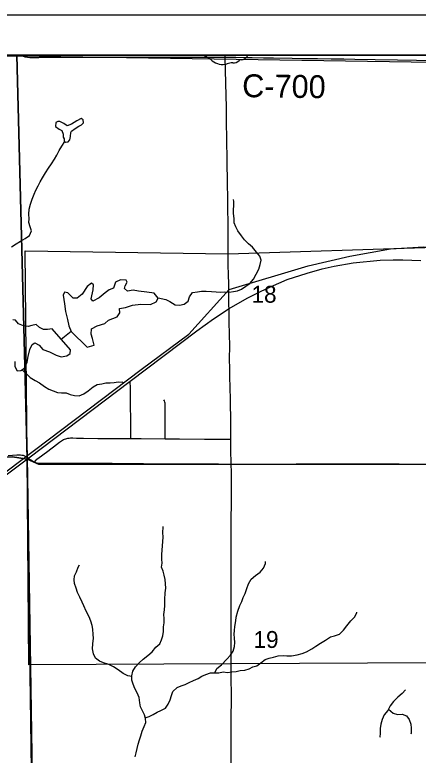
# Model space of a CAD drawing. Extents: x 0 to 34, y 0 to 22.
# Drawn here: x 3.028 to 4.028, y 19.165 to 21 of the extents above; entities that cross this region are included whole.
import ezdxf

# ---------------------------------------------------------------- set-up
doc = ezdxf.new("R2010")
doc.units = 0
for name, color, linetype in [('Default', 7, 'Continuous'), ('GM_X_City_Street', 7, 'Continuous'), ('GM_X_Corporation', 7, 'Continuous'), ('GM_X_Corporation_Text', 7, 'Continuous'), ('GM_X_County_Road', 7, 'Continuous'), ('GM_X_County_Road_Text', 7, 'Continuous'), ('GM_X_Interstate_Route', 7, 'Continuous'), ('GM_X_Minor_Lake', 7, 'Continuous'), ('GM_X_Minor_River', 7, 'Continuous'), ('GM_X_Rail_Line', 7, 'Continuous'), ('GM_X_Section', 7, 'Continuous'), ('GM_X_Section_Text', 7, 'Continuous'), ('GM_X_State_Route', 7, 'Continuous'), ('GM_X_Township_Road', 7, 'Continuous'), ('SH_Cut_Line', 7, 'Continuous'), ('SH_Data', 7, 'Continuous')]:
    doc.layers.add(name, color=color, linetype=linetype)

msp = doc.modelspace()

# ---------------------------------------------------------------- linework, layer by layer
at = {"layer": 'Default'}
for points in [[(3.0341, 20.9), (2.1, 20.9), (2.1, 20.8702), (2.5271, 20.8724), (2.8601, 20.8963), (3.0341, 20.898)], [(2.1, 20.8702), (2.1, 19.8813), (2.4888, 19.8857), (3.0228, 19.9046), (3.0592, 19.8987), (3.0341, 20.898), (2.8601, 20.8963), (2.5271, 20.8724)], [(4.0643, 20.9), (3.0341, 20.9), (3.0341, 20.898), (4.0647, 20.8827)], [(2.1, 19.8813), (2.1, 18.8733), (3.073, 18.8909), (3.0592, 19.8987), (3.0228, 19.9046), (2.4888, 19.8857)]]:
    msp.add_lwpolyline(points, close=True, dxfattribs=at)
at = {"layer": 'GM_X_City_Street'}
for points in [[(3.3157, 19.9496), (3.3159, 19.9674), (3.3146, 20.0609), (3.3145, 20.0765), (3.3144, 20.089), (3.3143, 20.0921)], [(3.4004, 19.949), (3.4005, 19.9557), (3.4008, 19.987), (3.4011, 20.0276), (3.401, 20.0339), (3.4008, 20.037), (3.4002, 20.04), (3.3989, 20.0429), (3.3972, 20.0457)], [(3.0772, 19.8914), (3.0802, 19.8952), (3.0831, 19.8983), (3.0853, 19.9003), (3.1099, 19.9184), (3.1172, 19.9239), (3.1244, 19.9293), (3.1391, 19.9403), (3.1466, 19.9456), (3.1491, 19.9471), (3.1517, 19.9483), (3.1542, 19.9493), (3.1569, 19.95), (3.1598, 19.9505), (3.1628, 19.9509), (3.1658, 19.951), (3.172, 19.9511), (3.1809, 19.9509), (3.198, 19.9507), (3.2336, 19.9501), (3.252, 19.95), (3.2862, 19.9498), (3.3157, 19.9496), (3.3409, 19.9495), (3.4004, 19.949), (3.4021, 19.949), (3.4363, 19.9491), (3.4985, 19.9484), (3.539, 19.9482), (3.5545, 19.9479), (3.5636, 19.9478)]]:
    msp.add_lwpolyline(points, dxfattribs=at)
at = {"layer": 'GM_X_Corporation'}
msp.add_lwpolyline([(4.0712, 19.394), (3.5643, 19.3915), (3.0631, 19.3888), (3.0588, 19.9042), (3.0542, 20.415), (3.5567, 20.4072), (4.0701, 20.4238), (4.0786, 19.8867)], close=True, dxfattribs=at)
at = {"layer": 'GM_X_Corporation_Text'}
msp.add_line((3.6067, 20.9), (3.493, 20.9), dxfattribs=at)
for centre, radius, start, end in [((3.4744, 20.8396), 0.0632, 47.1842, 72.9177), ((3.5428, 20.9169), 0.0401, 230.7004, 286.2918), ((3.5689, 20.9019), 0.0214, 268.777, 315.5493), ((3.5882, 20.8826), 0.00601, 65.7517, 132.6484), ((3.5856, 20.9101), 0.0226, 282.8732, 323.2771), ((3.6342, 20.8733), 0.0383, 135.8731, 142.5768), ((3.5659, 20.8477), 0.0329, 85.6951, 111.21)]:
    msp.add_arc(centre, radius, start, end, dxfattribs=at)
at = {"layer": 'GM_X_County_Road'}
for points in [[(3.5498, 20.8951), (3.5761, 20.8947), (3.5948, 20.8943), (3.6165, 20.894), (3.6444, 20.8934), (3.6693, 20.8931), (3.7159, 20.8923), (3.7407, 20.8918), (3.778, 20.8913), (3.8121, 20.8908), (3.8432, 20.8905), (3.8712, 20.89), (3.9209, 20.8893), (3.9768, 20.888), (4.0234, 20.8873), (4.0575, 20.8869)], [(3.0114, 19.908), (3.0331, 19.909), (3.0423, 19.9089), (3.0455, 19.9087), (3.0485, 19.9084), (3.0524, 19.9071), (3.056, 19.9055), (3.059, 19.9036)], [(3.059, 19.9036), (3.0641, 19.8994), (3.0666, 19.8975), (3.0692, 19.8957), (3.0747, 19.8925), (3.0772, 19.8914)], [(3.0772, 19.8914), (3.0805, 19.8901), (3.0836, 19.8893), (3.0868, 19.8888), (3.0899, 19.8886), (3.1117, 19.8884), (3.1488, 19.8885), (3.1705, 19.8884), (3.1984, 19.8883), (3.2294, 19.8882), (3.2697, 19.8883), (3.31, 19.8878), (3.3472, 19.8874), (3.4092, 19.887), (3.4433, 19.887), (3.4805, 19.8867), (3.5332, 19.8867), (3.5641, 19.886)], [(3.5641, 19.886), (3.5756, 19.8859), (3.5943, 19.886), (3.6161, 19.8861), (3.6566, 19.8863), (3.7251, 19.8868), (3.7624, 19.8868), (3.7935, 19.8869), (3.834, 19.8871), (3.8776, 19.8872), (3.9118, 19.8871), (3.9803, 19.8869), (4.0788, 19.8862)]]:
    msp.add_lwpolyline(points, dxfattribs=at)
at = {"layer": 'GM_X_Interstate_Route'}
msp.add_lwpolyline([(3.0331, 20.9), (2.1, 20.9), (2.1, 16.8784), (2.6014, 16.878), (3.0939, 16.8719), (3.0724, 18.2926), (3.0747, 18.8969), (3.067, 19.3838), (3.0588, 19.9042)], close=True, dxfattribs=at)
msp.add_lwpolyline([(8.1285, 16.8707), (8.1148, 17.8694), (8.0976, 18.2853), (8.0958, 18.3144), (8.0817, 18.88), (8.0959, 19.2713), (8.1023, 19.3817), (8.0929, 19.6339), (8.0678, 20.8562), (8.0675, 20.8733), (8.067, 20.8954), (8.0669, 20.9), (3.0331, 20.9), (3.0588, 19.9042), (3.067, 19.3838), (3.0747, 18.8969), (3.0724, 18.2926), (3.0939, 16.8719)], dxfattribs=at)
at = {"layer": 'GM_X_Minor_Lake'}
for points in [[(3.1534, 20.6844), (3.1606, 20.6854), (3.1645, 20.6903), (3.1664, 20.6986), (3.1669, 20.7085), (3.1684, 20.7115), (3.1776, 20.7183), (3.1871, 20.7239), (3.1932, 20.7276), (3.1982, 20.7321), (3.1975, 20.7393), (3.1926, 20.7428), (3.1819, 20.7372), (3.1686, 20.7286), (3.158, 20.7249), (3.1497, 20.7303), (3.1395, 20.7353), (3.1346, 20.7358), (3.1296, 20.7328), (3.1292, 20.7233), (3.1382, 20.7164), (3.1446, 20.7129), (3.1479, 20.7038), (3.1482, 20.6969), (3.1501, 20.6924), (3.1504, 20.687)], [(3.1504, 20.687), (3.1534, 20.6844)]]:
    msp.add_lwpolyline(points, dxfattribs=at)
at = {"layer": 'GM_X_Minor_River'}
for points in [[(3.0198, 20.4246), (3.0316, 20.4325), (3.0423, 20.4392), (3.0541, 20.4455), (3.0644, 20.453), (3.0694, 20.4647), (3.0665, 20.4742), (3.0631, 20.4849), (3.0636, 20.4944), (3.0633, 20.5061), (3.0638, 20.5179), (3.0669, 20.5304), (3.0712, 20.5432), (3.0762, 20.5553), (3.0805, 20.5655), (3.0863, 20.5761), (3.0913, 20.5859), (3.097, 20.5957), (3.1043, 20.6086), (3.112, 20.6195), (3.1193, 20.6308), (3.1266, 20.6425), (3.1323, 20.6523), (3.1385, 20.664), (3.1447, 20.6746), (3.1521, 20.6856)], [(3.3833, 20.2983), (3.4027, 20.2942), (3.4125, 20.2895), (3.4253, 20.2814), (3.4367, 20.2802), (3.448, 20.2827), (3.4579, 20.2902), (3.4607, 20.3008), (3.4687, 20.3114), (3.4812, 20.3135), (3.4907, 20.3146), (3.5021, 20.3148), (3.5153, 20.3143), (3.5388, 20.3126), (3.5486, 20.3129), (3.5596, 20.3128), (3.5699, 20.3138), (3.5797, 20.316), (3.59, 20.32), (3.601, 20.3272), (3.6105, 20.3343), (3.6193, 20.3448), (3.6266, 20.3573), (3.6328, 20.3697), (3.6359, 20.3807), (3.6383, 20.392), (3.6354, 20.4019), (3.6271, 20.4115), (3.617, 20.4237), (3.6072, 20.4326), (3.5975, 20.4425), (3.59, 20.4521), (3.581, 20.4647), (3.5761, 20.4742), (3.5721, 20.4845), (3.5714, 20.4951), (3.5704, 20.5073), (3.5704, 20.5172), (3.5709, 20.5266), (3.571, 20.5369), (3.5703, 20.5422)], [(3.2074, 20.1762), (3.2245, 20.1813), (3.2205, 20.1977), (3.2176, 20.2087), (3.218, 20.2216), (3.2325, 20.2294), (3.2511, 20.2346), (3.2606, 20.2432), (3.2819, 20.2513), (3.2881, 20.2615), (3.2878, 20.2718), (3.3022, 20.2743), (3.32, 20.2805), (3.3405, 20.2826), (3.3643, 20.282), (3.3788, 20.2887), (3.3838, 20.2978), (3.3737, 20.3096), (3.3551, 20.3125), (3.3343, 20.3146), (3.3215, 20.317), (3.3071, 20.3148), (3.2999, 20.3217), (3.3015, 20.3282), (3.3069, 20.3372), (3.3039, 20.3418), (3.2899, 20.3434), (3.2781, 20.3375), (3.273, 20.322), (3.2617, 20.3183), (3.2518, 20.3112), (3.2369, 20.2984), (3.2213, 20.2902), (3.2172, 20.296), (3.2227, 20.3183), (3.2228, 20.3308), (3.2183, 20.335), (3.2072, 20.3264), (3.1949, 20.3072), (3.1827, 20.2974), (3.1725, 20.2979), (3.1597, 20.3106), (3.151, 20.3125), (3.1479, 20.305), (3.1515, 20.2833), (3.154, 20.2643), (3.1588, 20.2449), (3.1621, 20.229), (3.1676, 20.2153)], [(3.028, 20.1407), (3.0283, 20.1278), (3.0339, 20.1171), (3.043, 20.1182), (3.0525, 20.1238), (3.0591, 20.1389), (3.0615, 20.1529), (3.0658, 20.1703), (3.0712, 20.1828), (3.078, 20.1865), (3.0886, 20.1811), (3.0979, 20.17), (3.1138, 20.1649), (3.1304, 20.156), (3.1429, 20.1518), (3.1569, 20.1543), (3.1653, 20.1606), (3.1665, 20.1694), (3.1204, 20.2218), (3.109, 20.2196), (3.0991, 20.2201), (3.089, 20.2251), (3.0811, 20.232), (3.0701, 20.2295), (3.061, 20.2277), (3.05, 20.2289), (3.0375, 20.2343), (3.03, 20.2431), (3.0236, 20.244)], [(3.1433, 20.1957), (3.1675, 20.2155)], [(3.1676, 20.2153), (3.2074, 20.1762)], [(3.0464, 20.1202), (3.0663, 20.1009), (3.0787, 20.0939), (3.0893, 20.0874), (3.1021, 20.0789), (3.1123, 20.072), (3.1236, 20.0677), (3.1338, 20.0634), (3.1436, 20.0633), (3.1557, 20.0629), (3.1655, 20.059), (3.1765, 20.0566), (3.1879, 20.0553), (3.1993, 20.0602), (3.2103, 20.0676), (3.2221, 20.0781), (3.232, 20.0837), (3.2442, 20.0855), (3.2536, 20.0873), (3.2642, 20.088), (3.2748, 20.0883), (3.2847, 20.0901), (3.2957, 20.0896), (3.2945, 20.0884)], [(3.3945, 19.6834), (3.3949, 19.6941), (3.3958, 19.7051), (3.3951, 19.7168), (3.3956, 19.7301), (3.396, 19.732)], [(3.3268, 19.161), (3.3287, 19.1708), (3.3318, 19.181), (3.3342, 19.1924), (3.3373, 19.2026), (3.3404, 19.2124), (3.344, 19.2245), (3.349, 19.2359), (3.3525, 19.2461), (3.3518, 19.2556), (3.3496, 19.2651), (3.3444, 19.2746), (3.3396, 19.2849), (3.3377, 19.2948), (3.336, 19.3077), (3.3311, 19.3191), (3.3252, 19.3302), (3.3215, 19.3405), (3.3182, 19.3511), (3.3182, 19.3617), (3.321, 19.3731), (3.3275, 19.3836), (3.3367, 19.3938), (3.3462, 19.4024), (3.3577, 19.4118), (3.3687, 19.4212), (3.3779, 19.4328), (3.3878, 19.4407), (3.3921, 19.4505), (3.3952, 19.4604), (3.3964, 19.4717), (3.3965, 19.4827), (3.3981, 19.4926), (3.3986, 19.5036), (3.3975, 19.5135), (3.3992, 19.5248), (3.4, 19.5358), (3.3998, 19.5506), (3.401, 19.5669), (3.4023, 19.5787), (3.402, 19.5893), (3.4009, 19.6003), (3.3984, 19.6106), (3.3958, 19.6212), (3.3921, 19.6307), (3.393, 19.641), (3.3923, 19.6508), (3.3928, 19.6622), (3.3932, 19.6728), (3.3945, 19.6834)], [(3.5238, 19.3692), (3.5289, 19.3794), (3.5404, 19.3884), (3.5538, 19.4027), (3.5629, 19.4125), (3.5691, 19.4223), (3.5726, 19.4344), (3.5734, 19.4442), (3.5728, 19.4549), (3.5721, 19.4647), (3.5729, 19.4742), (3.5738, 19.4841), (3.5758, 19.4977), (3.5766, 19.5072), (3.5809, 19.5215), (3.5856, 19.5355), (3.5906, 19.5453), (3.5937, 19.5552), (3.5994, 19.5654), (3.6033, 19.5782), (3.6076, 19.5892), (3.6141, 19.6009), (3.6248, 19.6103), (3.6366, 19.6185), (3.6443, 19.6283), (3.6497, 19.64), (3.6497, 19.6449)], [(3.3182, 19.3595), (3.308, 19.3615), (3.2967, 19.3669), (3.2839, 19.3765), (3.2726, 19.3834), (3.2609, 19.3896), (3.2481, 19.3939), (3.2383, 19.3978), (3.2281, 19.4051), (3.2229, 19.4158), (3.2211, 19.4283), (3.2216, 19.4408), (3.2229, 19.4545), (3.2226, 19.4639), (3.2215, 19.4769), (3.2197, 19.4864), (3.2168, 19.4966), (3.2127, 19.508), (3.2053, 19.5218), (3.1993, 19.5347), (3.1948, 19.5443), (3.1889, 19.5568), (3.1837, 19.5683), (3.18, 19.5785), (3.1763, 19.59), (3.1749, 19.5998), (3.1765, 19.6097), (3.1807, 19.6195), (3.1854, 19.6308), (3.1888, 19.6369)], [(3.3513, 19.2576), (3.3609, 19.2604), (3.3712, 19.2652), (3.3807, 19.2716), (3.3902, 19.2753), (3.4016, 19.2809), (3.4078, 19.2914), (3.4128, 19.3016), (3.4167, 19.313), (3.4198, 19.3228), (3.4305, 19.3329), (3.4403, 19.3363), (3.4506, 19.3403), (3.4605, 19.3448), (3.4711, 19.35), (3.4825, 19.3552), (3.492, 19.3604), (3.5019, 19.3649), (3.5133, 19.3689), (3.5243, 19.3692), (3.5341, 19.3687), (3.5448, 19.3717), (3.555, 19.3701), (3.5656, 19.3711), (3.577, 19.3721), (3.5865, 19.3747), (3.5978, 19.3753), (3.6088, 19.3786), (3.6183, 19.3835), (3.6278, 19.3864), (3.6377, 19.3939), (3.6484, 19.4021), (3.6587, 19.4055), (3.6689, 19.408), (3.6807, 19.4113), (3.6928, 19.412), (3.7026, 19.4111), (3.7136, 19.411), (3.728, 19.4135), (3.7406, 19.4168), (3.7512, 19.4209), (3.7641, 19.428), (3.7744, 19.4347), (3.7858, 19.4425), (3.7984, 19.4496), (3.8106, 19.4579), (3.8208, 19.4608), (3.8326, 19.4648), (3.8425, 19.475), (3.8506, 19.4855), (3.8605, 19.4976), (3.8701, 19.507), (3.8755, 19.5179), (3.8755, 19.5191)], [(3.9965, 19.3271), (3.9885, 19.3173), (3.9771, 19.3087), (3.9667, 19.2981), (3.9583, 19.2868), (3.9529, 19.2759), (3.9434, 19.265), (3.9387, 19.2529), (3.9352, 19.2415), (3.9332, 19.2313), (3.9335, 19.2196), (3.933, 19.2097), (3.9338, 19.2101)], [(3.9546, 19.2792), (3.9654, 19.2686), (3.9767, 19.2658), (3.9877, 19.2665), (3.9986, 19.2626), (4.0057, 19.253), (4.0094, 19.2416), (4.0105, 19.2321), (4.01, 19.2196), (4.0092, 19.2169)]]:
    msp.add_lwpolyline(points, dxfattribs=at)
at = {"layer": 'GM_X_Rail_Line'}
for points in [[(2.1, 19.1903), (2.2176, 19.2766), (2.3422, 19.3707), (2.5003, 19.4885), (2.7369, 19.665), (2.944, 19.8207), (3.3415, 20.1206), (3.4596, 20.2081), (3.5596, 20.3194), (3.7554, 20.3776), (3.8584, 20.4014), (3.9589, 20.4196), (4.0414, 20.4251), (4.3012, 20.4183), (4.3584, 20.4251), (4.4262, 20.4416), (4.5028, 20.4697), (4.9465, 20.6634), (5.0176, 20.7062), (5.0741, 20.7492), (5.1326, 20.8127), (5.1783, 20.8803), (5.1912, 20.9)], [(2.1, 19.1763), (2.3025, 19.329), (2.5005, 19.4778), (2.9171, 19.7925), (3.0629, 19.9022), (3.3144, 20.0919), (3.4796, 20.2167), (3.5208, 20.2463), (3.5593, 20.2719), (3.6039, 20.2977), (3.6372, 20.3142), (3.6622, 20.326), (3.7035, 20.3435), (3.7526, 20.3598), (3.7901, 20.3703), (3.8195, 20.3771), (3.8669, 20.3851), (3.934, 20.3918), (3.9658, 20.3929), (3.9898, 20.3929), (4.0344, 20.3908)]]:
    msp.add_lwpolyline(points, dxfattribs=at)
at = {"layer": 'GM_X_Section'}
for points in [[(4.0647, 20.8827), (4.0799, 19.8852), (3.0869, 19.8862), (3.0592, 19.8987), (3.0341, 20.898)], [(4.0799, 19.8852), (4.08, 18.8834), (3.073, 18.8909), (3.0592, 19.8987), (3.0869, 19.8862)]]:
    msp.add_lwpolyline(points, close=True, dxfattribs=at)
at = {"layer": 'GM_X_State_Route'}
for points in [[(3.5569, 20.4067), (3.5569, 20.434), (3.5569, 20.4604), (3.5557, 20.5428), (3.5555, 20.5839), (3.5546, 20.6361), (3.5534, 20.6939), (3.5531, 20.7326), (3.5525, 20.7705), (3.5514, 20.8309), (3.5498, 20.8951), (3.5497, 20.8989), (3.5496, 20.9)], [(3.5585, 20.3181), (3.5584, 20.3365), (3.5581, 20.3521), (3.5571, 20.3838), (3.5569, 20.4067)], [(3.559, 20.2712), (3.5589, 20.2793), (3.5586, 20.3084), (3.5585, 20.3181)], [(3.5641, 19.886), (3.5636, 19.9227), (3.5636, 19.9403), (3.5636, 19.9478), (3.5636, 19.9517), (3.5636, 19.9708), (3.5633, 19.9915), (3.5624, 20.0423), (3.5621, 20.0804), (3.5614, 20.0981), (3.5614, 20.1073), (3.5613, 20.1228), (3.5606, 20.1476), (3.561, 20.1787), (3.5594, 20.2377), (3.559, 20.2712)], [(3.5645, 19.6228), (3.5644, 19.6858), (3.5644, 19.7169), (3.5647, 19.7531), (3.565, 19.7851), (3.565, 19.8118), (3.5648, 19.851), (3.5648, 19.8662), (3.5641, 19.886)], [(3.5645, 19.3909), (3.5644, 19.4148), (3.5647, 19.4708), (3.5647, 19.5468), (3.5645, 19.6228)], [(3.5648, 19.2948), (3.5648, 19.3056), (3.5645, 19.3646), (3.5645, 19.3909)], [(3.5645, 19.1347), (3.5646, 19.2652), (3.5648, 19.2948)]]:
    msp.add_lwpolyline(points, dxfattribs=at)
at = {"layer": 'GM_X_Township_Road'}
msp.add_lwpolyline([(3.0421, 20.9), (3.0474, 20.8979), (3.0534, 20.8961), (3.0596, 20.895), (3.0658, 20.8945), (3.0721, 20.8943), (3.0877, 20.8943), (3.125, 20.8946), (3.1654, 20.8949), (3.1871, 20.8947), (3.2182, 20.8947), (3.2369, 20.8949), (3.2649, 20.8951), (3.2991, 20.895), (3.3426, 20.8951), (3.383, 20.8949), (3.4265, 20.8948), (3.4825, 20.8948), (3.5105, 20.8946), (3.5292, 20.8949), (3.5447, 20.895), (3.5498, 20.8951)], dxfattribs=at)
at = {"layer": 'SH_Cut_Line'}
msp.add_lwpolyline([(8.1285, 16.8707), (8.1148, 17.8694), (8.0976, 18.2853), (8.0958, 18.3144), (8.0817, 18.88), (8.0959, 19.2713), (8.1023, 19.3817), (8.0929, 19.6339), (8.0678, 20.8562), (8.0675, 20.8733), (8.067, 20.8954), (8.0669, 20.9), (2.1, 20.9), (2.1, 14.1)], dxfattribs=at)
at = {"layer": 'SH_Data'}
for p, q in [((2, 21), (9, 21)), ((2.1, 20.9), (8.9, 20.9))]:
    msp.add_line(p, q, dxfattribs=at)

# ---------------------------------------------------------------- texts
at = {"layer": 'GM_X_County_Road_Text'}
msp.add_text('C-700', height=0.05682, rotation=359.1834, dxfattribs=at).set_placement((3.5913, 20.796))
at = {"layer": 'GM_X_Section_Text'}
for s, p in [('18', (3.6146, 20.2864)), ('19', (3.6196, 19.4306))]:
    msp.add_text(s, height=0.04186, rotation=0, dxfattribs=at).set_placement(p)

doc.saveas('drawing.dxf')
